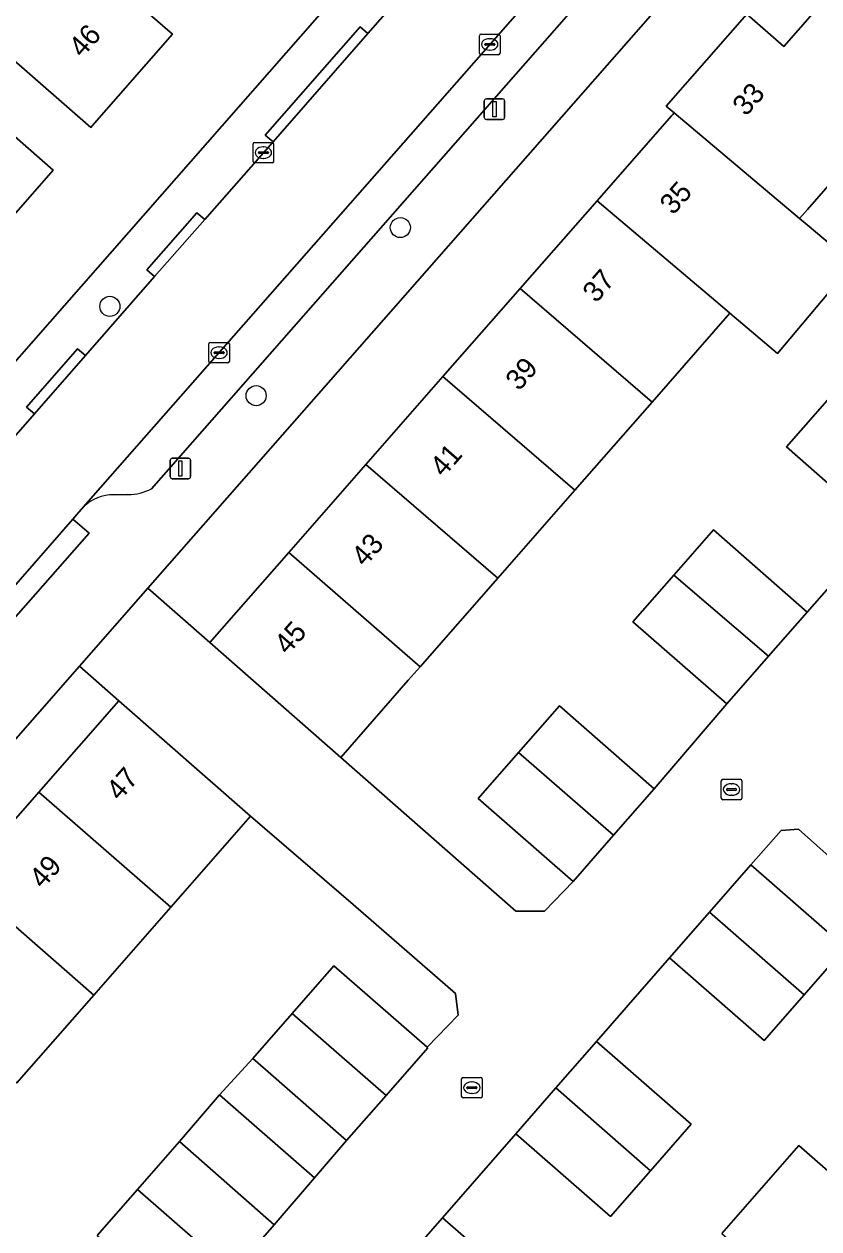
# Model space of a CAD drawing. Extents: x 158472 to 159562, y 388525 to 389606.
# Drawn here: x 158789.8 to 158828.5, y 388856.6 to 388915.3 of the extents above; entities that cross this region are included whole.
import ezdxf

# ---------------------------------------------------------------- set-up
doc = ezdxf.new("R2010")
doc.units = 0
for name, color, linetype in [('IMGEO_Boom', 7, 'Continuous'), ('IMGEO_Erf', 7, 'Continuous'), ('IMGEO_Kolk', 7, 'Continuous'), ('IMGEO_Lichtmast', 7, 'Continuous'), ('IMGEO_Muur', 7, 'Continuous'), ('IMGEO_Pand', 7, 'Continuous'), ('IMGEO_Pand_nummerreeks', 7, 'Continuous'), ('IMGEO_Parkeervlak_open', 7, 'Continuous'), ('IMGEO_Rijbaan_lokaal_open', 7, 'Continuous'), ('IMGEO_Voetpad_open', 7, 'Continuous')]:
    doc.layers.add(name, color=color, linetype=linetype)

msp = doc.modelspace()

# ---------------------------------------------------------------- linework, layer by layer
at = {"layer": 'IMGEO_Boom'}
for centre in [(158808.138, 388905.391), (158793.979, 388901.55), (158801.107, 388897.195)]:
    msp.add_circle(centre, 0.489, dxfattribs=at)
at = {"layer": 'IMGEO_Erf'}
for points in [[(158762.962, 388868.767), (158769.386, 388876.091), (158775.72, 388883.311), (158826.285, 388940.957)], [(158825.253, 388921.341), (158795.826, 388887.817), (158798.849, 388885.154), (158802.702, 388889.551), (158806.459, 388893.84), (158810.215, 388898.126), (158813.971, 388902.413), (158817.729, 388906.703), (158821.349, 388910.834), (158821.398, 388910.89), (158821.482, 388910.986), (158821.097, 388911.311), (158825.031, 388915.802), (158826.829, 388914.227), (158828.932, 388916.627)], [(158793.138, 388918.224), (158797.03, 388914.824), (158793.12, 388910.355), (158793.044, 388910.268), (158789.16, 388913.666)], [(158787.338, 388911.582), (158791.208, 388908.196), (158787.256, 388903.678)], [(158830.234, 388908.841), (158827.987, 388906.277), (158827.722, 388905.974), (158827.598, 388905.833), (158827.972, 388905.518), (158830.207, 388903.635), (158826.516, 388899.255), (158824.202, 388901.216), (158820.409, 388896.886), (158816.649, 388892.595), (158812.885, 388888.298), (158809.102, 388883.98), (158808.526, 388883.323), (158805.231, 388879.562), (158813.764, 388872.059), (158815.161, 388872.061), (158816.561, 388873.514), (158811.939, 388877.563), (158813.901, 388879.802), (158815.889, 388882.071), (158820.511, 388878.023), (158824.047, 388882.165), (158819.475, 388886.171), (158821.471, 388888.45), (158823.4, 388890.651), (158827.972, 388886.645), (158831.53, 388890.69), (158826.96, 388894.694), (158829.063, 388897.095)], [(158786.764, 388873.586), (158790.519, 388877.871), (158794.414, 388882.316), (158792.495, 388884.015), (158770.012, 388858.352)], [(158793.361, 388856.252), (158795.318, 388858.486), (158797.367, 388860.824), (158799.322, 388863.111), (158800.945, 388864.885), (158802.866, 388867.078), (158804.902, 388869.402), (158809.443, 388865.424), (158810.963, 388866.998), (158810.828, 388868.055), (158805.839, 388872.384), (158800.837, 388876.689), (158797.542, 388872.929), (158796.948, 388872.251), (158793.194, 388867.966), (158789.449, 388863.692)], [(158823.814, 388856.35), (158827.567, 388860.634), (158830.013, 388858.491), (158833.764, 388862.78), (158831.433, 388864.849), (158835.318, 388869.207), (158829.335, 388874.47), (158827.54, 388876.052), (158826.694, 388875.99), (158825.229, 388874.325), (158829.835, 388870.296), (158827.816, 388867.987), (158825.872, 388865.764), (158821.265, 388869.792), (158817.694, 388865.707), (158822.311, 388861.669), (158820.332, 388859.405), (158818.378, 388857.171), (158813.76, 388861.209), (158810.195, 388857.109), (158814.79, 388853.092)]]:
    msp.add_lwpolyline(points, dxfattribs=at)
at = {"layer": 'IMGEO_Kolk'}
for p, q in [((158811.996, 388913.895), (158811.996, 388914.747)), ((158812.071, 388914.821), (158812.923, 388914.821)), ((158812.255, 388914.315), (158812.255, 388914.327)), ((158812.693, 388914.278), (158812.295, 388914.278)), ((158812.298, 388914.364), (158812.696, 388914.364)), ((158812.484, 388914.601), (158812.509, 388914.601)), ((158812.739, 388914.327), (158812.739, 388914.315)), ((158812.997, 388914.747), (158812.997, 388913.895)), ((158812.923, 388913.821), (158812.071, 388913.821)), ((158812.507, 388914.041), (158812.482, 388914.041)), ((158800.962, 388908.619), (158800.962, 388909.471)), ((158801.037, 388909.545), (158801.889, 388909.545)), ((158801.221, 388909.039), (158801.221, 388909.051)), ((158801.659, 388909.002), (158801.261, 388909.002)), ((158801.264, 388909.088), (158801.662, 388909.088)), ((158801.45, 388909.325), (158801.475, 388909.325)), ((158801.705, 388909.051), (158801.705, 388909.039)), ((158801.963, 388909.471), (158801.963, 388908.619)), ((158801.889, 388908.545), (158801.037, 388908.545)), ((158801.473, 388908.765), (158801.448, 388908.765)), ((158798.802, 388898.865), (158798.802, 388899.717)), ((158798.877, 388899.791), (158799.729, 388899.791)), ((158799.803, 388899.717), (158799.803, 388898.865)), ((158799.061, 388899.285), (158799.061, 388899.297)), ((158799.499, 388899.248), (158799.101, 388899.248)), ((158799.104, 388899.334), (158799.502, 388899.334)), ((158799.313, 388899.011), (158799.288, 388899.011)), ((158799.29, 388899.571), (158799.315, 388899.571)), ((158799.545, 388899.297), (158799.545, 388899.285)), ((158799.729, 388898.791), (158798.877, 388898.791)), ((158823.857, 388878.494), (158824.709, 388878.494)), ((158823.782, 388877.568), (158823.782, 388878.42)), ((158824.041, 388877.988), (158824.041, 388878)), ((158824.479, 388877.951), (158824.081, 388877.951)), ((158824.084, 388878.037), (158824.482, 388878.037)), ((158824.27, 388878.274), (158824.295, 388878.274)), ((158824.525, 388878), (158824.525, 388877.988)), ((158824.783, 388878.42), (158824.783, 388877.568)), ((158824.709, 388877.494), (158823.857, 388877.494)), ((158824.293, 388877.714), (158824.268, 388877.714)), ((158811.124, 388863.028), (158811.124, 388863.88)), ((158811.199, 388863.954), (158812.051, 388863.954)), ((158812.125, 388863.88), (158812.125, 388863.028)), ((158811.383, 388863.448), (158811.383, 388863.46)), ((158811.821, 388863.411), (158811.423, 388863.411)), ((158811.426, 388863.497), (158811.824, 388863.497)), ((158811.635, 388863.174), (158811.61, 388863.174)), ((158811.612, 388863.734), (158811.637, 388863.734)), ((158811.867, 388863.46), (158811.867, 388863.448)), ((158812.051, 388862.954), (158811.199, 388862.954))]:
    msp.add_line(p, q, dxfattribs=at)
for points in [[(158811.996, 388913.895), (158811.996, 388914.747)], [(158812.071, 388914.821), (158812.923, 388914.821)], [(158812.997, 388914.747), (158812.997, 388913.895)], [(158812.923, 388913.821), (158812.071, 388913.821)], [(158800.962, 388908.619), (158800.962, 388909.471)], [(158801.037, 388909.545), (158801.889, 388909.545)], [(158801.963, 388909.471), (158801.963, 388908.619)], [(158801.889, 388908.545), (158801.037, 388908.545)], [(158798.802, 388898.865), (158798.802, 388899.717)], [(158798.877, 388899.791), (158799.729, 388899.791)], [(158799.803, 388899.717), (158799.803, 388898.865)], [(158799.729, 388898.791), (158798.877, 388898.791)], [(158823.857, 388878.494), (158824.709, 388878.494)], [(158823.782, 388877.568), (158823.782, 388878.42)], [(158824.783, 388878.42), (158824.783, 388877.568)], [(158824.709, 388877.494), (158823.857, 388877.494)], [(158811.124, 388863.028), (158811.124, 388863.88)], [(158811.199, 388863.954), (158812.051, 388863.954)], [(158812.125, 388863.88), (158812.125, 388863.028)], [(158812.051, 388862.954), (158811.199, 388862.954)]]:
    msp.add_lwpolyline(points, dxfattribs=at)
for centre, radius, start, end in [((158812.073, 388914.745), 0.0765, 91.55205, 178.44795), ((158812.073, 388914.745), 0.0765, 91.55205, 178.44795), ((158812.295, 388914.324), 0.0403, 85.87752, 175.75265), ((158812.292, 388914.314), 0.0366, 178.93798, 274.71019), ((158812.696, 388914.321), 0.043, 264.86636, 352.45326), ((158812.7, 388914.326), 0.0386, 1.73085, 96.63898), ((158812.921, 388914.745), 0.0765, 1.55205, 88.44795), ((158812.921, 388914.745), 0.0765, 1.55205, 88.44795), ((158812.073, 388913.897), 0.0765, 181.55205, 268.44795), ((158812.073, 388913.897), 0.0765, 181.55205, 268.44795), ((158812.921, 388913.897), 0.0765, 271.55205, 358.44795), ((158812.921, 388913.897), 0.0765, 271.55205, 358.44795), ((158801.039, 388909.469), 0.0765, 91.55205, 178.44795), ((158801.039, 388909.469), 0.0765, 91.55205, 178.44795), ((158801.261, 388909.048), 0.0403, 85.87752, 175.75265), ((158801.258, 388909.038), 0.0366, 178.93798, 274.71019), ((158801.662, 388909.045), 0.043, 264.86636, 352.45326), ((158801.666, 388909.05), 0.0386, 1.73085, 96.63898), ((158801.887, 388909.469), 0.0765, 1.55205, 88.44795), ((158801.887, 388909.469), 0.0765, 1.55205, 88.44795), ((158801.039, 388908.621), 0.0765, 181.55205, 268.44795), ((158801.039, 388908.621), 0.0765, 181.55205, 268.44795), ((158801.887, 388908.621), 0.0765, 271.55205, 358.44795), ((158801.887, 388908.621), 0.0765, 271.55205, 358.44795), ((158798.879, 388899.715), 0.0765, 91.55205, 178.44795), ((158798.879, 388899.715), 0.0765, 91.55205, 178.44795), ((158799.727, 388899.715), 0.0765, 1.55205, 88.44795), ((158799.727, 388899.715), 0.0765, 1.55205, 88.44795), ((158799.101, 388899.294), 0.0403, 85.87752, 175.75265), ((158799.098, 388899.284), 0.0366, 178.93798, 274.71019), ((158799.502, 388899.291), 0.043, 264.86636, 352.45326), ((158799.506, 388899.296), 0.0386, 1.73085, 96.63898), ((158798.879, 388898.867), 0.0765, 181.55205, 268.44795), ((158798.879, 388898.867), 0.0765, 181.55205, 268.44795), ((158799.727, 388898.867), 0.0765, 271.55205, 358.44795), ((158799.727, 388898.867), 0.0765, 271.55205, 358.44795), ((158823.859, 388878.418), 0.0765, 91.55205, 178.44795), ((158823.859, 388878.418), 0.0765, 91.55205, 178.44795), ((158824.707, 388878.418), 0.0765, 1.55205, 88.44795), ((158824.707, 388878.418), 0.0765, 1.55205, 88.44795), ((158824.081, 388877.997), 0.0403, 85.87752, 175.75265), ((158824.078, 388877.987), 0.0366, 178.93798, 274.71019), ((158824.482, 388877.994), 0.043, 264.86636, 352.45326), ((158824.486, 388877.999), 0.0386, 1.73085, 96.63898), ((158823.859, 388877.57), 0.0765, 181.55205, 268.44795), ((158823.859, 388877.57), 0.0765, 181.55205, 268.44795), ((158824.707, 388877.57), 0.0765, 271.55205, 358.44795), ((158824.707, 388877.57), 0.0765, 271.55205, 358.44795), ((158811.201, 388863.878), 0.0765, 91.55205, 178.44795), ((158811.201, 388863.878), 0.0765, 91.55205, 178.44795), ((158812.049, 388863.878), 0.0765, 1.55205, 88.44795), ((158812.049, 388863.878), 0.0765, 1.55205, 88.44795), ((158811.423, 388863.457), 0.0403, 85.87752, 175.75265), ((158811.42, 388863.447), 0.0366, 178.93798, 274.71019), ((158811.824, 388863.454), 0.043, 264.86636, 352.45326), ((158811.828, 388863.459), 0.0386, 1.73085, 96.63898), ((158811.201, 388863.03), 0.0765, 181.55205, 268.44795), ((158811.201, 388863.03), 0.0765, 181.55205, 268.44795), ((158812.049, 388863.03), 0.0765, 271.55205, 358.44795), ((158812.049, 388863.03), 0.0765, 271.55205, 358.44795)]:
    msp.add_arc(centre, radius, start, end, dxfattribs=at)
for centre, major_axis, ratio, start_param, end_param in [((158812.483, 388914.321), (-0.387, 0.002), 0.722429, 4.712389, 7.853982), ((158812.508, 388914.321), (-0.39, 0.002), 0.717154, 1.570796, 4.712389), ((158801.449, 388909.045), (-0.387, 0.002), 0.722429, 4.712389, 7.853982), ((158801.474, 388909.045), (-0.39, 0.002), 0.717154, 1.570796, 4.712389), ((158799.289, 388899.291), (-0.387, 0.002), 0.722429, 4.712389, 7.853982), ((158799.314, 388899.291), (-0.39, 0.002), 0.717154, 1.570796, 4.712389), ((158824.269, 388877.994), (-0.387, 0.002), 0.722429, 4.712389, 7.853982), ((158824.294, 388877.994), (-0.39, 0.002), 0.717154, 1.570796, 4.712389), ((158811.611, 388863.454), (-0.387, 0.002), 0.722429, 4.712389, 7.853982), ((158811.636, 388863.454), (-0.39, 0.002), 0.717154, 1.570796, 4.712389)]:
    msp.add_ellipse(centre, major_axis=major_axis, ratio=ratio, start_param=start_param, end_param=end_param, dxfattribs=at)
at = {"layer": 'IMGEO_Lichtmast'}
for p, q in [((158812.232, 388910.765), (158812.232, 388911.565)), ((158812.232, 388911.565), (158812.232, 388910.765)), ((158812.332, 388911.665), (158813.122, 388911.665)), ((158813.122, 388911.665), (158812.332, 388911.665)), ((158813.222, 388911.565), (158813.222, 388910.765)), ((158813.222, 388910.765), (158813.222, 388911.565)), ((158813.122, 388910.665), (158812.332, 388910.665)), ((158812.332, 388910.665), (158813.122, 388910.665)), ((158796.922, 388893.247), (158796.922, 388894.047)), ((158796.922, 388894.047), (158796.922, 388893.247)), ((158797.022, 388894.147), (158797.812, 388894.147)), ((158797.812, 388894.147), (158797.022, 388894.147)), ((158797.912, 388894.047), (158797.912, 388893.247)), ((158797.912, 388893.247), (158797.912, 388894.047)), ((158797.812, 388893.147), (158797.022, 388893.147)), ((158797.022, 388893.147), (158797.812, 388893.147))]:
    msp.add_line(p, q, dxfattribs=at)
for points in [[(158812.652, 388911.54), (158812.802, 388911.54), (158812.802, 388910.79), (158812.652, 388910.79), (158812.652, 388911.54)], [(158797.342, 388894.022), (158797.492, 388894.022), (158797.492, 388893.272), (158797.342, 388893.272), (158797.342, 388894.022)]]:
    msp.add_lwpolyline(points, dxfattribs=at)
for centre, start, end in [((158812.332, 388911.565), 90, 180), ((158812.332, 388911.565), 90, 180), ((158813.122, 388911.565), 0, 90), ((158813.122, 388911.565), 360, 90), ((158812.332, 388910.765), 180, 270), ((158812.332, 388910.765), 180, 270), ((158813.122, 388910.765), 270, 0), ((158813.122, 388910.765), 270, 0), ((158797.022, 388894.047), 90, 180), ((158797.022, 388894.047), 90, 180), ((158797.812, 388894.047), 0, 90), ((158797.812, 388894.047), 360, 90), ((158797.022, 388893.247), 180, 270), ((158797.022, 388893.247), 180, 270), ((158797.812, 388893.247), 270, 0), ((158797.812, 388893.247), 270, 0)]:
    msp.add_arc(centre, 0.1, start, end, dxfattribs=at)
at = {"layer": 'IMGEO_Muur'}
msp.add_lwpolyline([(158810.195, 388857.109), (158813.76, 388861.209)], dxfattribs=at)
at = {"layer": 'IMGEO_Pand'}
for points in [[(158789.16, 388913.666), (158793.044, 388910.268), (158793.12, 388910.355), (158797.03, 388914.824), (158793.138, 388918.224), (158795.023, 388920.378), (158789.067, 388925.507), (158785.613, 388921.559), (158783.238, 388918.777)], [(158789.16, 388913.666), (158783.238, 388918.777), (158779.787, 388914.833), (158782.017, 388912.883), (158779.839, 388910.393), (158779.654, 388910.181), (158784.034, 388906.434), (158787.256, 388903.678), (158791.208, 388908.196), (158787.338, 388911.582)], [(158821.482, 388910.986), (158827.598, 388905.833), (158827.722, 388905.974), (158827.987, 388906.277), (158830.234, 388908.841), (158833.528, 388912.601), (158828.932, 388916.627), (158826.829, 388914.227), (158825.031, 388915.802), (158821.097, 388911.311)], [(158821.482, 388910.986), (158821.398, 388910.89), (158821.349, 388910.834), (158817.729, 388906.703), (158823.728, 388901.618), (158824.202, 388901.216), (158826.516, 388899.255), (158830.207, 388903.635), (158827.972, 388905.518), (158827.598, 388905.833)], [(158817.729, 388906.703), (158813.971, 388902.413), (158820.409, 388896.886), (158824.202, 388901.216), (158823.728, 388901.618)], [(158820.409, 388896.886), (158813.971, 388902.413), (158810.215, 388898.126), (158816.649, 388892.595)], [(158812.885, 388888.298), (158816.649, 388892.595), (158810.215, 388898.126), (158806.459, 388893.84)], [(158829.063, 388897.095), (158826.96, 388894.694), (158831.53, 388890.69), (158833.699, 388893.166)], [(158809.102, 388883.98), (158812.885, 388888.298), (158806.459, 388893.84), (158802.702, 388889.551)], [(158826.081, 388884.487), (158827.972, 388886.645), (158823.4, 388890.651), (158821.471, 388888.45)], [(158809.102, 388883.98), (158802.702, 388889.551), (158798.849, 388885.154), (158805.231, 388879.562), (158808.526, 388883.323)], [(158826.081, 388884.487), (158821.471, 388888.45), (158819.475, 388886.171), (158824.047, 388882.165)], [(158796.948, 388872.251), (158797.542, 388872.929), (158800.837, 388876.689), (158794.414, 388882.316), (158790.519, 388877.871)], [(158818.536, 388875.768), (158820.511, 388878.023), (158815.889, 388882.071), (158813.901, 388879.802)], [(158818.536, 388875.768), (158813.901, 388879.802), (158811.939, 388877.563), (158816.561, 388873.514)], [(158796.948, 388872.251), (158790.519, 388877.871), (158786.764, 388873.586), (158793.194, 388867.966)], [(158827.816, 388867.987), (158829.835, 388870.296), (158825.229, 388874.325), (158823.211, 388872.018)], [(158786.764, 388873.586), (158783.158, 388869.47), (158782.772, 388869.807), (158782.625, 388869.639), (158789.053, 388864.037), (158789.449, 388863.692), (158793.194, 388867.966)], [(158827.816, 388867.987), (158823.211, 388872.018), (158821.265, 388869.792), (158825.872, 388865.764)], [(158804.902, 388869.402), (158802.866, 388867.078), (158807.441, 388863.078), (158809.473, 388865.398), (158809.443, 388865.424)], [(158801.559, 388864.347), (158805.515, 388860.88), (158807.441, 388863.078), (158802.866, 388867.078), (158800.945, 388864.885)], [(158815.721, 388863.451), (158820.332, 388859.405), (158822.311, 388861.669), (158817.694, 388865.707)], [(158801.559, 388864.347), (158800.945, 388864.885), (158799.322, 388863.111), (158799.984, 388862.525), (158803.952, 388859.055), (158805.515, 388860.88)], [(158815.721, 388863.451), (158813.76, 388861.209), (158818.378, 388857.171), (158820.332, 388859.405)], [(158803.952, 388859.055), (158799.984, 388862.525), (158799.322, 388863.111), (158797.367, 388860.824), (158801.994, 388856.77)], [(158799.95, 388854.437), (158801.994, 388856.77), (158797.367, 388860.824), (158795.318, 388858.486)], [(158830.013, 388858.491), (158827.567, 388860.634), (158823.814, 388856.35), (158826.262, 388854.201), (158826.421, 388854.062), (158832.658, 388848.588), (158836.414, 388852.883)], [(158799.95, 388854.437), (158795.318, 388858.486), (158793.361, 388856.252), (158797.993, 388852.204)], [(158808.242, 388854.876), (158812.827, 388850.847), (158814.79, 388853.092), (158810.195, 388857.109)]]:
    msp.add_lwpolyline(points, close=True, dxfattribs=at)
at = {"layer": 'IMGEO_Parkeervlak_open'}
for points in [[(158819.644, 388919.58), (158818.213, 388920.836), (158792.7, 388891.773)], [(158796.009, 388892.657), (158819.644, 388919.58)], [(158794.164, 388892.36), (158794.86, 388892.379)]]:
    msp.add_lwpolyline(points, dxfattribs=at)
for centre, radius, start, end in [((158794.896, 388894.742), 2.363, 269.11868, 298.08392), ((158794.124, 388890.34), 2.02, 88.87086, 134.82639)]:
    msp.add_arc(centre, radius, start, end, dxfattribs=at)
at = {"layer": 'IMGEO_Rijbaan_lokaal_open'}
msp.add_lwpolyline([(158818.213, 388920.836), (158820.762, 388923.74), (158822.366, 388925.567), (158818.752, 388928.756), (158818.078, 388927.989), (158815.64, 388925.208), (158812.287, 388921.385), (158809.81, 388918.561), (158806.553, 388914.848), (158801.931, 388909.578), (158798.603, 388905.784), (158796.16, 388902.998), (158792.786, 388899.152), (158790.3, 388896.317), (158787.022, 388892.58), (158784.684, 388889.914), (158788.291, 388886.749), (158788.381, 388886.851), (158792.181, 388891.181), (158792.369, 388891.396), (158792.7, 388891.773)], close=True, dxfattribs=at)
for points in [[(158831.53, 388890.69), (158827.972, 388886.645), (158826.081, 388884.487), (158824.047, 388882.165), (158820.511, 388878.023), (158818.536, 388875.768), (158816.561, 388873.514), (158815.161, 388872.061), (158813.764, 388872.059), (158805.231, 388879.562), (158798.849, 388885.154), (158795.826, 388887.817), (158792.495, 388884.015), (158794.414, 388882.316), (158800.837, 388876.689), (158805.839, 388872.384), (158810.828, 388868.055), (158810.963, 388866.998), (158809.443, 388865.424), (158809.473, 388865.398), (158807.441, 388863.078), (158805.515, 388860.88), (158803.952, 388859.055), (158801.994, 388856.77), (158799.95, 388854.437)], [(158808.242, 388854.876), (158810.195, 388857.109), (158813.76, 388861.209), (158815.721, 388863.451), (158817.694, 388865.707), (158821.265, 388869.792), (158823.211, 388872.018), (158825.229, 388874.325), (158826.694, 388875.99), (158827.54, 388876.052), (158829.335, 388874.47)]]:
    msp.add_lwpolyline(points, dxfattribs=at)
at = {"layer": 'IMGEO_Voetpad_open'}
for points in [[(158826.285, 388940.957), (158775.72, 388883.311), (158769.386, 388876.091), (158762.962, 388868.767), (158762.869, 388868.63), (158759.244, 388864.12)], [(158792.495, 388884.015), (158795.826, 388887.817), (158825.253, 388921.341), (158832.871, 388930.074), (158837.191, 388935.033), (158839.072, 388938.341), (158839.072, 388938.84), (158838.808, 388938.843)], [(158828.018, 388929.12), (158822.193, 388922.484), (158822.571, 388922.158), (158820.131, 388919.378), (158819.753, 388919.704), (158819.644, 388919.58), (158796.009, 388892.657)], [(158777.383, 388881.589), (158777.005, 388881.915), (158779.495, 388884.754), (158779.873, 388884.428), (158782.604, 388887.543), (158784.415, 388889.608), (158784.535, 388889.744), (158784.157, 388890.07), (158786.644, 388892.906), (158787.022, 388892.58), (158790.3, 388896.317), (158789.921, 388896.642), (158792.407, 388899.477), (158792.786, 388899.152), (158796.16, 388902.998), (158795.781, 388903.323), (158798.224, 388906.109), (158798.603, 388905.784), (158801.931, 388909.578), (158801.553, 388909.904), (158806.175, 388915.174), (158806.553, 388914.848), (158809.81, 388918.561)], [(158794.86, 388892.379), (158794.164, 388892.36)], [(158792.7, 388891.773), (158792.369, 388891.396), (158792.181, 388891.181), (158792.963, 388890.495), (158789.163, 388886.165), (158788.381, 388886.851), (158788.291, 388886.749), (158788.228, 388886.677)], [(158757.25, 388848.258), (158763.289, 388850.678), (158770.012, 388858.352), (158792.495, 388884.015)]]:
    msp.add_lwpolyline(points, dxfattribs=at)
for points in [[(158806.553, 388914.848), (158806.175, 388915.174), (158801.553, 388909.904), (158801.931, 388909.578)], [(158796.16, 388902.998), (158798.603, 388905.784), (158798.224, 388906.109), (158795.781, 388903.323)], [(158790.3, 388896.317), (158792.786, 388899.152), (158792.407, 388899.477), (158789.921, 388896.642)], [(158792.181, 388891.181), (158788.381, 388886.851), (158789.163, 388886.165), (158792.963, 388890.495)]]:
    msp.add_lwpolyline(points, close=True, dxfattribs=at)
for centre, radius, start, end in [((158794.896, 388894.742), 2.363, 269.11868, 298.08392), ((158794.124, 388890.34), 2.02, 88.87086, 134.82639)]:
    msp.add_arc(centre, radius, start, end, dxfattribs=at)

# ---------------------------------------------------------------- texts
at = {"layer": 'IMGEO_Pand_nummerreeks'}
for s, rotation, p in [('46', 48.8168, (158792.634, 388913.627)), ('33', 48.78163, (158824.986, 388910.775)), ('35', 48.7759, (158821.442, 388905.963)), ('37', 48.7759, (158817.684, 388901.674)), ('39', 48.77627, (158813.925, 388897.385)), ('41', 48.77627, (158810.241, 388893.18)), ('43', 48.77627, (158806.408, 388888.806)), ('45', 48.77627, (158802.65, 388884.517)), ('47', 48.77431, (158794.46, 388877.393)), ('49', 48.77431, (158790.708, 388873.111))]:
    msp.add_text(s, height=1, rotation=rotation, dxfattribs=at).set_placement(p)

doc.saveas('drawing.dxf')
